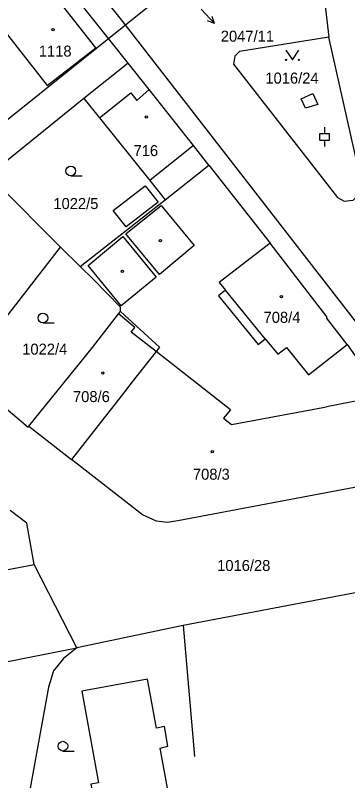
# Model space of a CAD drawing. Extents: x -794765 to -785424, y -1118958 to -1108731.
# Drawn here: x -792034.8 to -791983.5, y -1109922.9 to -1109804.8 of the extents above; entities that cross this region are included whole.
import ezdxf

# ---------------------------------------------------------------- set-up
doc = ezdxf.new("R2010")
doc.units = 0
for name, color, linetype in [('Level 66', 7, 'Continuous'), ('Level 71', 7, 'Continuous'), ('Level 75', 7, 'Continuous'), ('Level 76', 7, 'Continuous'), ('Level 77', 7, 'Continuous'), ('Level 79', 7, 'Continuous'), ('Level 80', 7, 'Continuous'), ('Level 81', 7, 'Continuous')]:
    doc.layers.add(name, color=color, linetype=linetype)

msp = doc.modelspace()

# ---------------------------------------------------------------- linework, layer by layer
at = {"layer": 'Level 66'}
for p, q in [((-791987.76, -1109823.02), (-791986.26, -1109823.02)), ((-791987.76, -1109824.02), (-791987.76, -1109823.02)), ((-791987.01, -1109823.02), (-791987.01, -1109822.02)), ((-791986.26, -1109824.02), (-791986.26, -1109823.02)), ((-791987.76, -1109824.02), (-791986.26, -1109824.02)), ((-791987.01, -1109825.02), (-791987.01, -1109824.02)), ((-792026.23, -1109829.52), (-792024.48, -1109829.52)), ((-792030.54, -1109852.22), (-792028.79, -1109852.22)), ((-792027.45, -1109918.3), (-792025.7, -1109918.3))]:
    msp.add_line(p, q, dxfattribs=at)
msp.add_lwpolyline([(-791993.01, -1109810.13), (-791992.01, -1109811.63), (-791991.01, -1109810.13)], dxfattribs=at)
for centre, radius in [((-791993.01, -1109811.63), 0.1), ((-791991.01, -1109811.63), 0.1), ((-792026.23, -1109828.77), 0.75), ((-792030.54, -1109851.47), 0.75), ((-792027.45, -1109917.55), 0.75)]:
    msp.add_circle(centre, radius, dxfattribs=at)
at = {"layer": 'Level 71'}
msp.add_lwpolyline([(-791938.08, -1109742.36), (-792598.01, -1110271.46), (-792786.15, -1110036.8), (-792126.22, -1109507.7)], close=True, dxfattribs=at)
at = {"layer": 'Level 75'}
for p, q in [((-792017.36, -1109812.14), (-792029.85, -1109796.46)), ((-791987.59, -1109797.65), (-791986.38, -1109808.14)), ((-791986.38, -1109808.14), (-792000.2, -1109810.35)), ((-791981.27, -1109830.8), (-791986.38, -1109808.14)), ((-792017.36, -1109812.14), (-792024.2, -1109817.62)), ((-792001.08, -1109812.3), (-791985.06, -1109832.85)), ((-792024.2, -1109817.62), (-792038.84, -1109829.36)), ((-792011.68, -1109833.21), (-792004.92, -1109827.88)), ((-792004.92, -1109827.88), (-791995.42, -1109839.94)), ((-792027.81, -1109840.52), (-792038.2, -1109830.14)), ((-792024.79, -1109843.54), (-792011.68, -1109833.21)), ((-792024.79, -1109843.54), (-792027.81, -1109840.52)), ((-792022.8, -1109845.46), (-792024.79, -1109843.54)), ((-792032.79, -1109868.31), (-792032.7, -1109868.19)), ((-792032.7, -1109868.19), (-792026.14, -1109873.31)), ((-792015.17, -1109881.83), (-792026.14, -1109873.31)), ((-792012.97, -1109882.81), (-792015.17, -1109881.83)), ((-792025.32, -1109902.4), (-792031.89, -1109889.51)), ((-791972.5, -1109892.05), (-792008.86, -1109898.91)), ((-792008.86, -1109898.91), (-792025.32, -1109902.4)), ((-792008.86, -1109898.91), (-792007.12, -1109919.15)), ((-792050.92, -1109907.37), (-792025.32, -1109902.4))]:
    msp.add_line(p, q, dxfattribs=at)
for points in [[(-791975.42, -1109863.21), (-791978.21, -1109857.78), (-791981.04, -1109853.58), (-792018.21, -1109805.69), (-792044.53, -1109772.76), (-792046.81, -1109769.82), (-792049.7, -1109767.06), (-792053.05, -1109764.88), (-792056.76, -1109763.28), (-792060.56, -1109762.21), (-792064.43, -1109761.57), (-792068.68, -1109761.68), (-792072.28, -1109762.62), (-792075.73, -1109764.16)], [(-792029.87, -1109815.6), (-792022.38, -1109809.77), (-792028.86, -1109801.47), (-792029.92, -1109802.3), (-792031.64, -1109800.09), (-792038.08, -1109805.1), (-792036.35, -1109807.31), (-792029.87, -1109815.6)], [(-792000.2, -1109810.35), (-792000.89, -1109811.07), (-792001.08, -1109812.3)], [(-792004.92, -1109827.88), (-792007.27, -1109824.85), (-792014.15, -1109816.23), (-792017.36, -1109812.14)], [(-792024.2, -1109817.62), (-792021.81, -1109820.6), (-792014.04, -1109830.27), (-792011.68, -1109833.21)], [(-791985.06, -1109832.85), (-791984.01, -1109833.45), (-791982.65, -1109833.27), (-791981.47, -1109832.2), (-791981.27, -1109830.8)], [(-792043.04, -1109860.14), (-792036.69, -1109851.96), (-792027.81, -1109840.52)], [(-791995.42, -1109839.94), (-792003.31, -1109845.98), (-792002.34, -1109847.16), (-792003.41, -1109848.04), (-791997.27, -1109855.55), (-791996.2, -1109854.68), (-791994.26, -1109857.06), (-791992.9, -1109856.04), (-791989.51, -1109860.23), (-791983.56, -1109855.58)], [(-791983.56, -1109855.58), (-791986.74, -1109851.45), (-791986.64, -1109851.36), (-791995.42, -1109839.94)], [(-792018.57, -1109850.46), (-792018.57, -1109849.8), (-792022.8, -1109845.46)], [(-792032.7, -1109868.19), (-792022.86, -1109856.03), (-792018.84, -1109850.81), (-792018.57, -1109850.46)], [(-792018.57, -1109850.46), (-792012.53, -1109855.99), (-792013.05, -1109856.65), (-792016.73, -1109861.34), (-792018.45, -1109863.53), (-792026.14, -1109873.31)], [(-791983.56, -1109855.58), (-791981.36, -1109858.72), (-791979.86, -1109863.81), (-791978.2, -1109863.45), (-791977.95, -1109864.76), (-791976.84, -1109870.56)], [(-792043.04, -1109860.14), (-792037.71, -1109864.22), (-792032.79, -1109868.31)], [(-791978.21, -1109874.59), (-791981.82, -1109875.29), (-791981.33, -1109877.41), (-792009.72, -1109882.75), (-792011.35, -1109883.02), (-792012.97, -1109882.81)], [(-792031.89, -1109889.51), (-792033.03, -1109883.15), (-792035.59, -1109881.18)], [(-792055.84, -1109894.11), (-792046.18, -1109892.24), (-792038.67, -1109890.81), (-792031.89, -1109889.51)], [(-792025.32, -1109902.4), (-792027.34, -1109904.01), (-792028.91, -1109905.95), (-792029.69, -1109908.43), (-792033.64, -1109930.28)], [(-792021.29, -1109926.93), (-792021.23, -1109927.25), (-792011.03, -1109925.41), (-792012.42, -1109917.86), (-792011.25, -1109917.57), (-792011.76, -1109914.54), (-792012.99, -1109914.77), (-792014.38, -1109907.21), (-792024.55, -1109909.04), (-792021.97, -1109923.19), (-792023.11, -1109923.4), (-792022.43, -1109927.14), (-792021.29, -1109926.93)]]:
    msp.add_lwpolyline(points, dxfattribs=at)
at = {"layer": 'Level 77'}
for p, q in [((-792021.81, -1109820.6), (-792016.96, -1109816.71)), ((-792016.96, -1109816.71), (-792016.01, -1109817.9)), ((-792016.01, -1109817.9), (-792014.15, -1109816.23)), ((-791990.68, -1109817.64), (-791988.85, -1109816.81)), ((-791988.85, -1109816.81), (-791988.06, -1109818.51)), ((-791990, -1109819.1), (-791990.68, -1109817.64)), ((-791988.06, -1109818.51), (-791990, -1109819.1)), ((-792007.27, -1109824.85), (-792014.04, -1109830.27)), ((-792019.67, -1109834.88), (-792014.72, -1109831.07)), ((-792014.72, -1109831.07), (-792012.75, -1109833.57)), ((-792012.75, -1109833.57), (-792017.67, -1109837.42)), ((-792017.67, -1109837.42), (-792019.67, -1109834.88)), ((-792017.71, -1109838.47), (-792012.27, -1109834.12)), ((-792012.27, -1109834.12), (-792007.17, -1109840.3)), ((-792012.55, -1109844.75), (-792017.71, -1109838.47)), ((-792023.53, -1109843.38), (-792018.19, -1109838.91)), ((-792018.19, -1109838.91), (-792013.05, -1109845.15)), ((-792007.17, -1109840.3), (-792012.55, -1109844.75)), ((-792018.43, -1109849.6), (-792023.53, -1109843.38)), ((-792013.05, -1109845.15), (-792018.43, -1109849.6)), ((-791996.2, -1109854.68), (-792002.34, -1109847.16)), ((-792016.34, -1109852.93), (-792018.84, -1109850.81)), ((-792016.89, -1109853.66), (-792016.34, -1109852.93)), ((-792013.05, -1109856.65), (-792016.89, -1109853.66)), ((-792001.59, -1109865.66), (-792013.05, -1109856.65)), ((-791979.86, -1109863.81), (-791986.75, -1109865.19)), ((-792001.59, -1109865.66), (-792002.64, -1109866.95)), ((-792001.4, -1109867.91), (-791986.75, -1109865.19)), ((-792002.64, -1109866.95), (-792001.4, -1109867.91))]:
    msp.add_line(p, q, dxfattribs=at)
at = {"layer": 'Level 79'}
for centre in [(-792028.97, -1109806.96), (-792014.58, -1109820.44), (-792012.39, -1109839.53), (-792018.29, -1109844.25), (-791993.71, -1109848.2), (-792021.28, -1109859.96), (-792004.38, -1109872.09)]:
    msp.add_circle(centre, 0.175, dxfattribs=at)
at = {"layer": 'Level 80'}
for p, q in [((-792006.11, -1109803.8), (-792004.06, -1109806)), ((-792004.06, -1109806), (-792004.38, -1109804.92)), ((-792004.06, -1109806), (-792005.11, -1109805.6))]:
    msp.add_line(p, q, dxfattribs=at)
at = {"layer": 'Level 81'}
msp.add_lwpolyline([(-792014.8, -1109810.08), (-792018.21, -1109805.69), (-792044.53, -1109772.76), (-792046.81, -1109769.82), (-792049.7, -1109767.06), (-792053.05, -1109764.88), (-792056.76, -1109763.28), (-792060.56, -1109762.21), (-792064.43, -1109761.57), (-792068.68, -1109761.68), (-792072.28, -1109762.62), (-792075.73, -1109764.16), (-792115.96, -1109792.85), (-792116.86, -1109794.88), (-792117.31, -1109797.12), (-792116.69, -1109800.34), (-792114.91, -1109802.94), (-792114.01, -1109804.07), (-792119.78, -1109808.18), (-792120.9, -1109806.8), (-792147.85, -1109825.45)], dxfattribs=at)

# ---------------------------------------------------------------- texts
at = {"layer": 'Level 76'}
for s, p in [('2047/11', (-792003.07, -1109808.83)), ('1118', (-792031.17, -1109811.13)), ('1016/24', (-791996.18, -1109815.3)), ('716', (-792016.54, -1109826.49)), ('1022/5', (-792028.92, -1109834.66)), ('708/4', (-791996.46, -1109852.22)), ('1022/4', (-792033.73, -1109857.13)), ('708/6', (-792025.89, -1109864.45)), ('708/3', (-792007.37, -1109876.43)), ('1016/28', (-792003.63, -1109890.52))]:
    msp.add_text(s, height=1.7, dxfattribs=at).set_placement(p)

doc.saveas('drawing.dxf')
